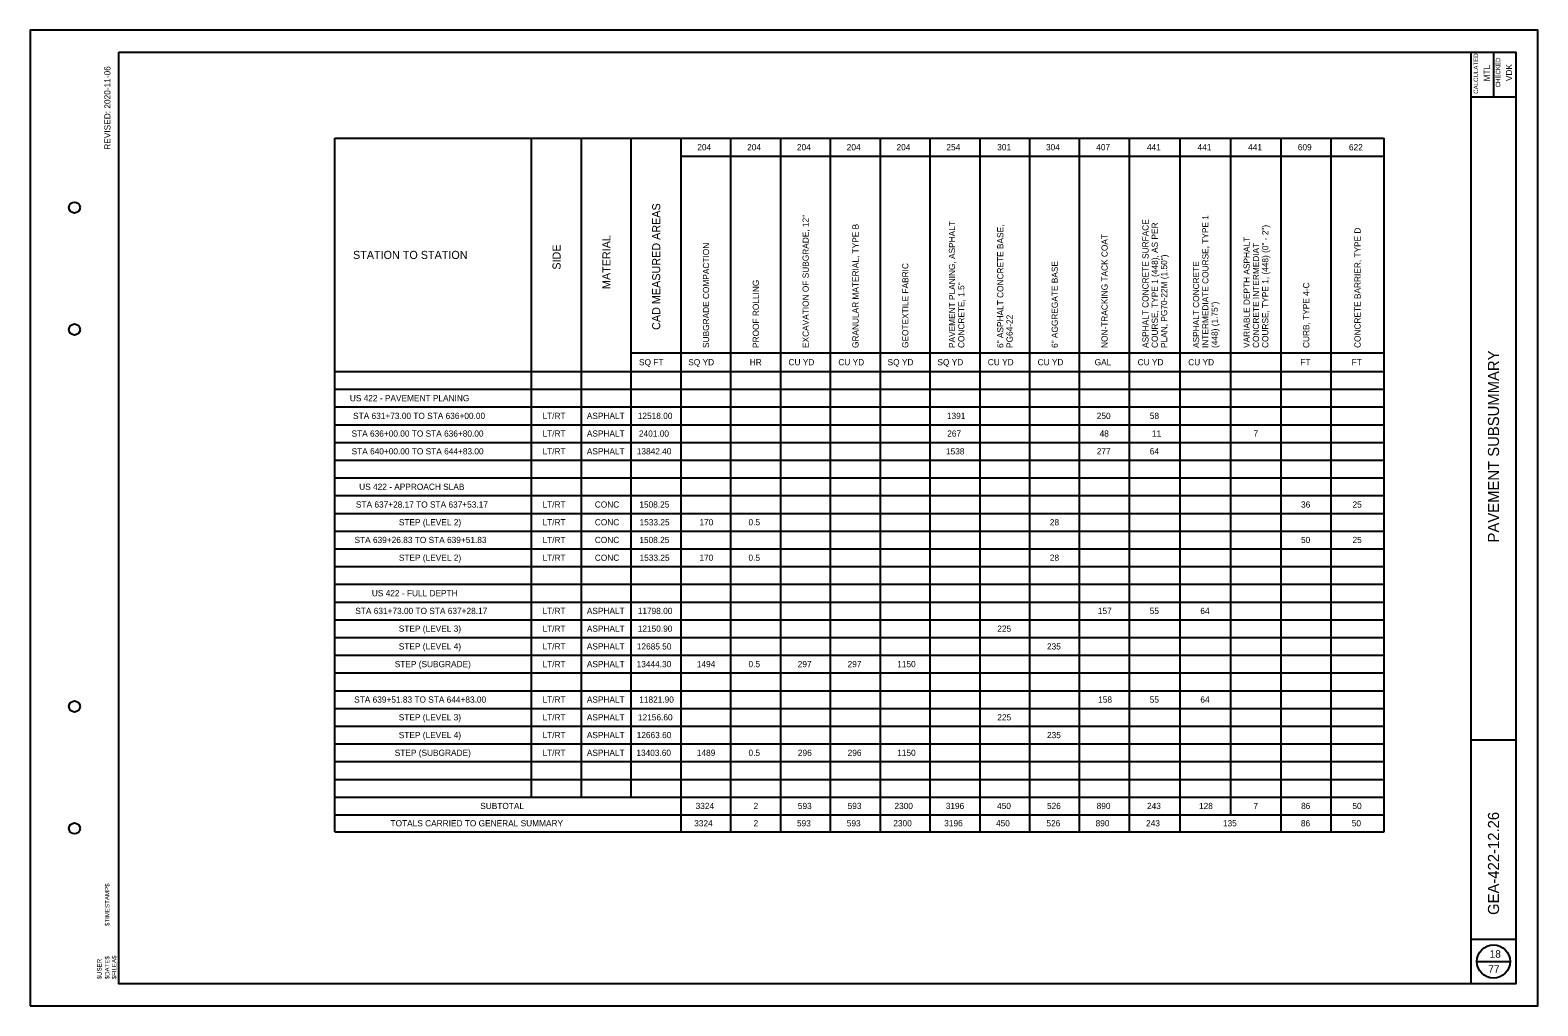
# Model space of a CAD drawing. Extents: x 0 to 34, y 0 to 22.
import ezdxf

# ---------------------------------------------------------------- set-up
doc = ezdxf.new("R2010")
doc.units = 0
for name, color, linetype in [('SH_Border', 7, 'Continuous'), ('SH_Cut_Line', 7, 'Continuous'), ('SH_Data', 7, 'Continuous'), ('SH_Text', 7, 'Continuous')]:
    doc.layers.add(name, color=color, linetype=linetype)

msp = doc.modelspace()

# ---------------------------------------------------------------- linework, layer by layer
at = {"layer": 'SH_Border'}
for p, q in [((32.5, 0.5), (32.5, 21.5)), ((33, 21.5), (33, 20.5)), ((32.5, 20.5), (33.5, 20.5)), ((32.5, 6), (33.5, 6)), ((32.5, 1.5), (33.5, 1.5))]:
    msp.add_line(p, q, dxfattribs=at)
msp.add_lwpolyline([(2, 21.5), (33.5, 21.5), (33.5, 0.5), (2, 0.5)], close=True, dxfattribs=at)
for centre in [(1, 18), (1, 15.25), (1, 6.75), (1, 4)]:
    msp.add_circle(centre, 0.125, dxfattribs=at)
at = {"layer": 'SH_Cut_Line'}
msp.add_lwpolyline([(0, 0), (34, 0), (34, 22), (0, 22)], close=True, dxfattribs=at)
at = {"layer": 'SH_Data'}
msp.add_line((32.625, 1), (33.375, 1), dxfattribs=at)
msp.add_circle((33, 1), 0.375, dxfattribs=at)
at = {"layer": 'SH_Text'}
for p, q in [((6.868, 19.561), (6.868, 19.561)), ((6.868, 19.561), (30.531, 19.561)), ((6.868, 3.927), (6.868, 19.561)), ((11.309, 4.707), (11.309, 19.561)), ((12.433, 4.707), (12.433, 19.561)), ((13.556, 4.707), (13.556, 19.561)), ((14.68, 3.927), (14.68, 19.561)), ((15.803, 3.927), (15.803, 19.561)), ((16.927, 3.927), (16.927, 19.561)), ((18.05, 3.927), (18.05, 19.561)), ((19.173, 3.927), (19.173, 19.561)), ((20.297, 3.927), (20.297, 19.561)), ((21.42, 3.927), (21.42, 19.561)), ((22.544, 3.927), (22.544, 19.561)), ((23.667, 3.927), (23.667, 19.561)), ((24.791, 3.927), (24.791, 19.561)), ((25.932, 3.927), (25.932, 19.561)), ((27.073, 4.307), (27.073, 19.561)), ((28.214, 3.927), (28.214, 19.561)), ((29.337, 3.927), (29.337, 19.561)), ((30.531, 3.927), (30.531, 19.561)), ((14.68, 19.161), (30.531, 19.161)), ((13.556, 14.723), (30.531, 14.723)), ((6.868, 14.303), (30.531, 14.303)), ((6.868, 13.903), (30.531, 13.903)), ((6.868, 13.503), (30.531, 13.503)), ((6.868, 13.103), (30.531, 13.103)), ((6.868, 12.704), (30.531, 12.704)), ((6.868, 12.304), (30.531, 12.304)), ((6.868, 11.904), (30.531, 11.904)), ((6.868, 11.504), (30.531, 11.504)), ((6.868, 11.104), (30.531, 11.104)), ((6.868, 10.704), (30.531, 10.704)), ((6.868, 10.305), (30.531, 10.305)), ((6.868, 9.905), (30.531, 9.905)), ((6.868, 9.505), (30.531, 9.505)), ((6.868, 9.105), (30.531, 9.105)), ((6.868, 8.705), (30.531, 8.705)), ((6.868, 8.305), (30.531, 8.305)), ((6.868, 7.906), (30.531, 7.906)), ((6.868, 7.506), (30.531, 7.506)), ((6.868, 7.106), (30.531, 7.106)), ((6.868, 6.706), (30.531, 6.706)), ((6.868, 6.306), (30.531, 6.306)), ((6.868, 5.906), (30.531, 5.906)), ((6.868, 5.507), (30.531, 5.507)), ((6.868, 5.107), (30.531, 5.107)), ((6.868, 4.707), (30.531, 4.707)), ((6.868, 4.307), (30.531, 4.307)), ((6.868, 3.927), (30.531, 3.927))]:
    msp.add_line(p, q, dxfattribs=at)

# ---------------------------------------------------------------- texts
at = {"layer": 'SH_Data'}
for s, height, rotation, p in [('CALCULATED', 0.1, 90, (32.652, 20.565)), ('MTL', 0.14, 90, (32.92, 20.844)), ('CHECKED', 0.1, 90, (33.152, 20.708)), ('VDK', 0.14, 90, (33.42, 20.851)), ('PAVEMENT SUBSUMMARY', 0.25, 90, (33.125, 10.449)), (' GEA-422-12.26 ', 0.25, 90, (33.125, 1.957)), ('$TIMESTAMP$', 0.1, 89.9931, (1.788, 1.8)), ('$USER', 0.1, 89.9931, (1.611, 0.598)), ('$DATE$', 0.1, 89.9931, (1.788, 0.598)), ('$FILEA$', 0.1, 89.9931, (1.944, 0.598))]:
    msp.add_text(s, height=height, rotation=rotation, dxfattribs=at).set_placement(p)
for s, p in [('18', (32.913, 1.085)), ('77', (32.882, 0.745))]:
    msp.add_text(s, height=0.17, dxfattribs=at).set_placement(p)
at = {"layer": 'SH_Text'}
for s, height, p in [('REVISED: 2020-11-06', 0.14, (1.811, 19.304)), ('CAD MEASURED AREAS', 0.182, (14.209, 15.242)), ('EXCAVATION OF SUBGRADE, 12"', 0.14, (17.558, 14.834)), ('PAVEMENT PLANING, ASPHALT', 0.14, (20.858, 14.833)), ('ASPHALT CONCRETE SURFACE', 0.14, (25.221, 14.834)), ('INTERMEDIATE COURSE, TYPE 1', 0.14, (26.572, 14.834)), ('MATERIAL', 0.182, (13.086, 16.162)), ('GRANULAR MATERIAL, TYPE B', 0.14, (18.682, 14.834)), ('6" ASPHALT CONCRETE BASE,', 0.14, (21.947, 14.834)), ('NON-TRACKING TACK COAT', 0.14, (24.299, 14.834)), ('COURSE, TYPE 1 (448), AS PER', 0.14, (25.431, 14.834)), ('COURSE, TYPE 1, (448) (0" - 2")', 0.14, (27.923, 14.834)), ('CONCRETE BARRIER, TYPE D', 0.14, (30.004, 14.834)), ('SIDE', 0.182, (11.962, 16.599)), ('SUBGRADE COMPACTION', 0.14, (15.311, 14.834)), ('VARIABLE DEPTH ASPHALT', 0.14, (27.503, 14.834)), ('CONCRETE INTERMEDIAT', 0.14, (27.713, 14.834)), ('GEOTEXTILE FABRIC', 0.14, (19.805, 14.834)), ('6" AGGREGATE BASE', 0.14, (23.175, 14.834)), ('PLAN, PG70-22M (1.50")', 0.14, (25.641, 14.834)), ('ASPHALT CONCRETE', 0.14, (26.362, 14.834)), ('PROOF ROLLING', 0.14, (16.435, 14.834)), ('CONCRETE, 1.5"', 0.14, (21.068, 14.833)), ('CURB, TYPE 4-C', 0.14, (28.845, 14.834)), ('(448) (1.75")', 0.14, (26.782, 14.834)), ('PG64-22', 0.14, (22.157, 14.834))]:
    msp.add_text(s, height=height, rotation=90, dxfattribs=at).set_placement(p)
for s, height, p in [('204', 0.14, (15.045, 19.291)), ('204', 0.14, (16.168, 19.291)), ('204', 0.14, (17.292, 19.291)), ('204', 0.14, (18.415, 19.291)), ('204', 0.14, (19.538, 19.291)), ('254', 0.14, (20.662, 19.291)), ('301', 0.14, (21.808, 19.291)), ('304', 0.14, (22.909, 19.291)), ('407', 0.14, (24.041, 19.291)), ('441', 0.14, (25.185, 19.291)), ('441', 0.14, (26.326, 19.291)), ('441', 0.14, (27.467, 19.291)), ('609', 0.14, (28.587, 19.291)), ('622', 0.14, (29.74, 19.291)), ('STATION TO STATION', 0.182, (7.281, 16.841)), ('SQ FT', 0.14, (13.731, 14.443)), ('SQ YD', 0.14, (14.842, 14.443)), ('HR', 0.14, (16.228, 14.443)), ('CU YD', 0.14, (17.102, 14.443)), ('CU YD', 0.14, (18.225, 14.443)), ('SQ YD', 0.14, (19.336, 14.443)), ('SQ YD', 0.14, (20.46, 14.443)), ('CU YD', 0.14, (21.596, 14.443)), ('CU YD', 0.14, (22.719, 14.443)), ('GAL', 0.14, (24.006, 14.443)), ('CU YD', 0.14, (24.975, 14.443)), ('CU YD', 0.14, (26.116, 14.443)), ('FT', 0.14, (28.644, 14.443)), ('FT', 0.14, (29.802, 14.443)), ('US 422 - PAVEMENT PLANING', 0.14, (7.209, 13.633)), ('STA 631+73.00 TO STA 636+00.00', 0.14, (7.283, 13.233)), ('LT/RT', 0.14, (11.554, 13.233)), ('ASPHALT', 0.14, (12.554, 13.233)), ('12518.00', 0.14, (13.703, 13.233)), ('1391', 0.14, (20.673, 13.233)), ('250', 0.14, (24.053, 13.233)), ('58', 0.14, (25.25, 13.233)), ('STA 636+00.00 TO STA 636+80.00', 0.14, (7.248, 12.834)), ('LT/RT', 0.14, (11.554, 12.834)), ('ASPHALT', 0.14, (12.554, 12.834)), ('2401.00', 0.14, (13.729, 12.834)), ('267', 0.14, (20.681, 12.834)), ('48', 0.14, (24.117, 12.834)), ('11', 0.14, (25.299, 12.834)), ('7', 0.14, (27.586, 12.834)), ('LT/RT', 0.14, (11.554, 12.434)), ('STA 640+00.00 TO STA 644+83.00', 0.14, (7.249, 12.434)), ('ASPHALT', 0.14, (12.554, 12.434)), ('13842.40', 0.14, (13.68, 12.434)), ('1538', 0.14, (20.653, 12.434)), ('277', 0.14, (24.053, 12.434)), ('64', 0.14, (25.248, 12.434)), ('US 422 - APPROACH SLAB', 0.14, (7.42, 11.634)), ('STA 637+28.17 TO STA 637+53.17', 0.14, (7.347, 11.234)), ('LT/RT', 0.14, (11.554, 11.234)), ('CONC', 0.14, (12.734, 11.234)), ('1508.25', 0.14, (13.738, 11.234)), ('36', 0.14, (28.66, 11.234)), ('25', 0.14, (29.821, 11.234)), ('STEP (LEVEL 2)', 0.14, (8.315, 10.834)), ('LT/RT', 0.14, (11.554, 10.834)), ('CONC', 0.14, (12.734, 10.834)), ('1533.25', 0.14, (13.743, 10.834)), ('170', 0.14, (15.093, 10.834)), ('0.5', 0.14, (16.199, 10.834)), ('28', 0.14, (22.995, 10.834)), ('STA 639+26.83 TO STA 639+51.83', 0.14, (7.315, 10.435)), ('LT/RT', 0.14, (11.554, 10.435)), ('CONC', 0.14, (12.734, 10.435)), ('1508.25', 0.14, (13.738, 10.435)), ('50', 0.14, (28.659, 10.435)), ('25', 0.14, (29.821, 10.435)), ('STEP (LEVEL 2)', 0.14, (8.315, 10.035)), ('LT/RT', 0.14, (11.554, 10.035)), ('CONC', 0.14, (12.734, 10.035)), ('1533.25', 0.14, (13.743, 10.035)), ('170', 0.14, (15.093, 10.035)), ('0.5', 0.14, (16.199, 10.035)), ('28', 0.14, (22.995, 10.035)), ('US 422 - FULL DEPTH', 0.14, (7.705, 9.235)), ('STA 631+73.00 TO STA 637+28.17', 0.14, (7.332, 8.835)), ('LT/RT', 0.14, (11.554, 8.835)), ('ASPHALT', 0.14, (12.554, 8.835)), ('11798.00', 0.14, (13.702, 8.835)), ('157', 0.14, (24.078, 8.835)), ('55', 0.14, (25.247, 8.835)), ('64', 0.14, (26.389, 8.835)), ('STEP (LEVEL 3)', 0.14, (8.313, 8.435)), ('LT/RT', 0.14, (11.554, 8.435)), ('ASPHALT', 0.14, (12.554, 8.435)), ('12150.90', 0.14, (13.702, 8.435)), ('225', 0.14, (21.81, 8.435)), ('STEP (LEVEL 4)', 0.14, (8.313, 8.035)), ('LT/RT', 0.14, (11.554, 8.035)), ('ASPHALT', 0.14, (12.554, 8.035)), ('12685.50', 0.14, (13.681, 8.035)), ('235', 0.14, (22.931, 8.035)), ('STEP (SUBGRADE)', 0.14, (8.222, 7.636)), ('LT/RT', 0.14, (11.554, 7.636)), ('ASPHALT', 0.14, (12.554, 7.636)), ('13444.30', 0.14, (13.677, 7.636)), ('1494', 0.14, (15.034, 7.636)), ('0.5', 0.14, (16.199, 7.636)), ('297', 0.14, (17.31, 7.636)), ('297', 0.14, (18.434, 7.636)), ('1150', 0.14, (19.553, 7.636)), ('STA 639+51.83 TO STA 644+83.00', 0.14, (7.307, 6.836)), ('LT/RT', 0.14, (11.554, 6.836)), ('ASPHALT', 0.14, (12.554, 6.836)), ('11821.90', 0.14, (13.736, 6.836)), ('158', 0.14, (24.085, 6.836)), ('55', 0.14, (25.247, 6.836)), ('64', 0.14, (26.389, 6.836)), ('STEP (LEVEL 3)', 0.14, (8.313, 6.436)), ('LT/RT', 0.14, (11.554, 6.436)), ('ASPHALT', 0.14, (12.554, 6.436)), ('12156.60', 0.14, (13.707, 6.436)), ('225', 0.14, (21.81, 6.436)), ('STEP (LEVEL 4)', 0.14, (8.313, 6.036)), ('LT/RT', 0.14, (11.554, 6.036)), ('ASPHALT', 0.14, (12.554, 6.036)), ('12663.60', 0.14, (13.678, 6.036)), ('235', 0.14, (22.931, 6.036)), ('STEP (SUBGRADE)', 0.14, (8.222, 5.636)), ('LT/RT', 0.14, (11.554, 5.636)), ('ASPHALT', 0.14, (12.554, 5.636)), ('13403.60', 0.14, (13.671, 5.636)), ('1489', 0.14, (15.034, 5.636)), ('0.5', 0.14, (16.199, 5.636)), ('296', 0.14, (17.313, 5.636)), ('296', 0.14, (18.436, 5.636)), ('1150', 0.14, (19.553, 5.636)), ('SUBTOTAL', 0.14, (10.15, 4.437)), ('3324', 0.14, (15.007, 4.437)), ('2', 0.14, (16.313, 4.437)), ('593', 0.14, (17.312, 4.437)), ('593', 0.14, (18.435, 4.437)), ('2300', 0.14, (19.491, 4.437)), ('3196', 0.14, (20.648, 4.437)), ('450', 0.14, (21.805, 4.437)), ('526', 0.14, (22.931, 4.437)), ('890', 0.14, (24.051, 4.437)), ('243', 0.14, (25.186, 4.437)), ('128', 0.14, (26.359, 4.437)), ('7', 0.14, (27.586, 4.437)), ('86', 0.14, (28.661, 4.437)), ('50', 0.14, (29.818, 4.437)), ('TOTALS CARRIED TO GENERAL SUMMARY', 0.14, (8.127, 4.047)), ('3324', 0.14, (14.975, 4.047)), ('2', 0.14, (16.313, 4.047)), ('593', 0.14, (17.292, 4.047)), ('593', 0.14, (18.416, 4.047)), ('2300', 0.14, (19.465, 4.047)), ('3196', 0.14, (20.613, 4.047)), ('450', 0.14, (21.781, 4.047)), ('526', 0.14, (22.919, 4.047)), ('890', 0.14, (24.027, 4.047)), ('243', 0.14, (25.165, 4.047)), ('135', 0.14, (26.898, 4.047)), ('86', 0.14, (28.657, 4.047)), ('50', 0.14, (29.804, 4.047))]:
    msp.add_text(s, height=height, dxfattribs=at).set_placement(p)

doc.saveas('drawing.dxf')
